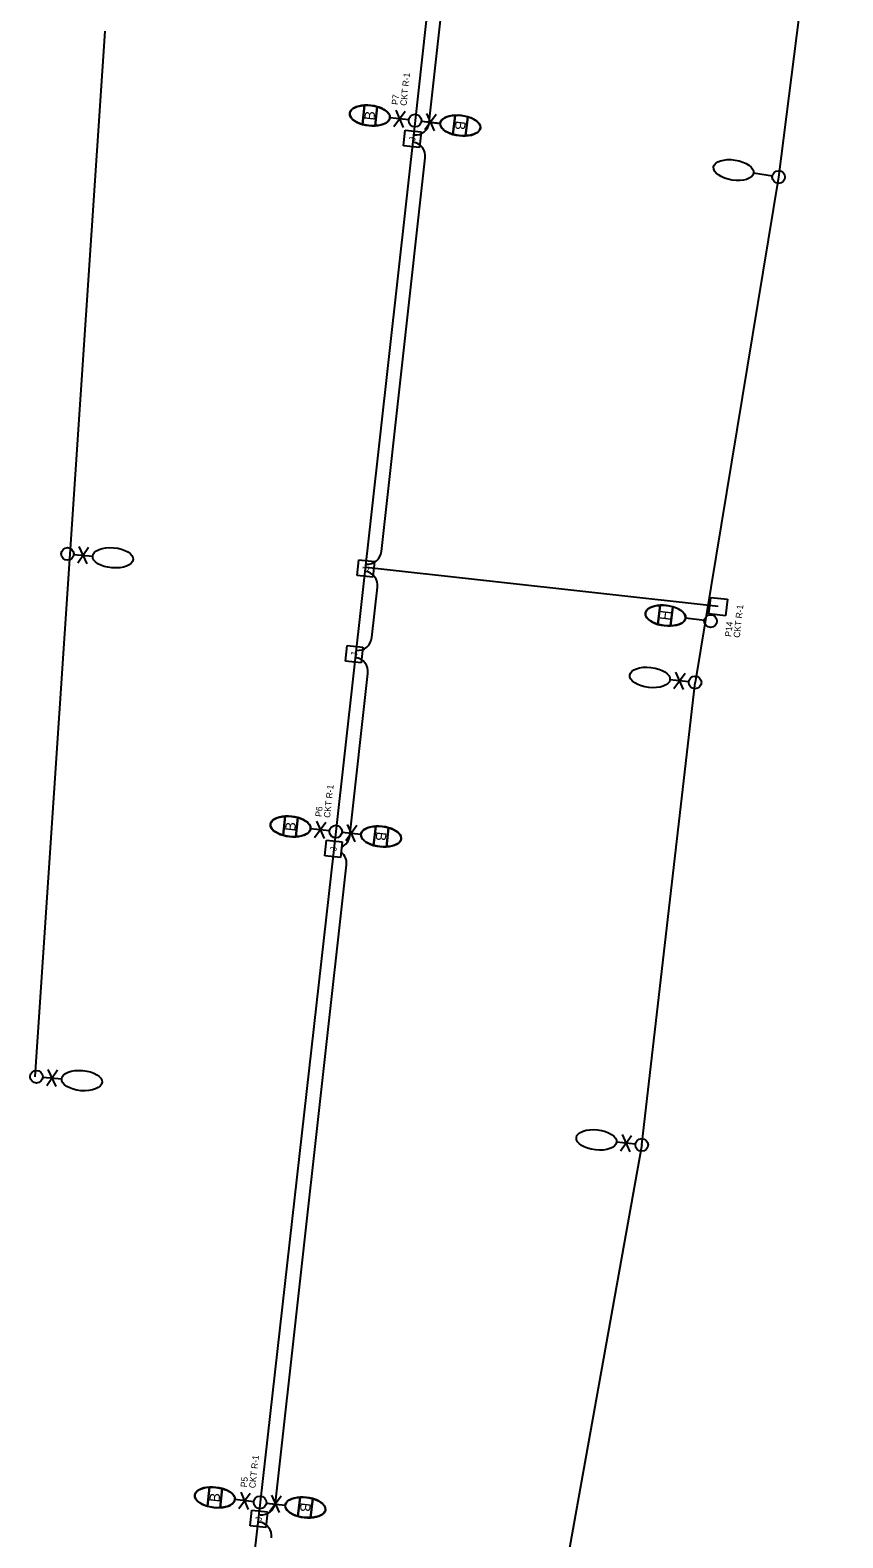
# Model space of a CAD drawing. Extents: x 925407 to 931638, y 609358 to 637063.
# Drawn here: x 930909 to 931227, y 622289 to 622880 of the extents above; entities that cross this region are included whole.
import ezdxf

# ---------------------------------------------------------------- set-up
doc = ezdxf.new("R2010")
doc.units = 0
for name, color, linetype in [('ActivePointCell_dp', 7, 'Continuous'), ('Conduit', 7, 'Continuous'), ('ConduitDB', 7, 'Continuous'), ('ConduitOT', 7, 'Continuous'), ('JunctBoxA', 7, 'Continuous'), ('LiteCond_ep', 7, 'Continuous'), ('Miscellaneous2', 7, 'Continuous'), ('PoleLight', 7, 'Continuous'), ('PoleLight_ep', 7, 'Continuous'), ('PullBox', 7, 'Continuous'), ('TextLabel', 7, 'Continuous')]:
    doc.layers.add(name, color=color, linetype=linetype)

msp = doc.modelspace()

# ---------------------------------------------------------------- linework, layer by layer
at = {"layer": 'Conduit'}
msp.add_line((931226.92, 623020.01), (931201.78, 622822.13), dxfattribs=at)
at = {"layer": 'ConduitDB'}
msp.add_line((931178.15, 622653.99), (931040.39, 622669.34), dxfattribs=at)
at = {"layer": 'ConduitOT'}
for p, q in [((931065.05, 622843.65), (931095.06, 623112.98)), ((931046.33, 622675.63), (931063.49, 622829.62)), ((931042.57, 622641.9), (931044.77, 622661.6)), ((931033.93, 622564.31), (931041.01, 622627.87)), ((931004.83, 622303.15), (931032.65, 622552.87))]:
    msp.add_line(p, q, dxfattribs=at)
for centre, start, end in [((931059.57, 622844.1), 264.8132, 355.29195), ((931058.03, 622830.35), 352.33293, 83.10011), ((931040.85, 622676.08), 264.8132, 355.29195), ((931039.31, 622662.33), 352.33293, 83.10011), ((931037.09, 622642.35), 264.8132, 355.29195), ((931035.55, 622628.6), 352.33293, 83.10011), ((931028.46, 622564.91), 295.25612, 353.6425), ((931027.19, 622553.48), 353.6425, 51.88491), ((930999.38, 622303.92), 264.8132, 351.99305), ((930997.85, 622290.17), 352.33293, 83.10011)]:
    msp.add_arc(centre, 5.5, start, end, dxfattribs=at)
at = {"layer": 'LiteCond_ep'}
for p, q in [((931090.52, 623122.74), (931059.5, 622844.27)), ((930910.79, 622469.96), (930938.27, 622879.32)), ((931059.5, 622844.27), (931028.48, 622565.95)), ((931201.78, 622822.13), (931169.11, 622624.29)), ((931148.21, 622443.26), (931169.11, 622624.29)), ((931028.48, 622565.95), (930998.82, 622303.42)), ((931148.21, 622443.26), (931092.21, 622130.66)), ((930998.82, 622303.42), (930969.37, 622039.11))]:
    msp.add_line(p, q, dxfattribs=at)
at = {"layer": 'Miscellaneous2'}
for p, q in [((931039.72, 622850.25), (931038.89, 622842.78)), ((931039.72, 622850.25), (931039.72, 622850.25)), ((931043.86, 622842.23), (931044.69, 622849.7)), ((931044.69, 622849.7), (931044.69, 622849.7)), ((931075.14, 622846.31), (931074.31, 622838.84)), ((931075.14, 622846.31), (931075.14, 622846.31)), ((931079.28, 622838.28), (931080.11, 622845.75)), ((931080.11, 622845.75), (931080.11, 622845.75)), ((931155.46, 622654.51), (931154.55, 622647.05)), ((931155.46, 622654.51), (931155.46, 622654.51)), ((931159.51, 622646.44), (931160.42, 622653.9)), ((931160.42, 622653.9), (931160.42, 622653.9)), ((931008.7, 622571.93), (931007.87, 622564.47)), ((931008.7, 622571.93), (931008.7, 622571.93)), ((931012.84, 622563.91), (931013.67, 622571.38)), ((931013.67, 622571.38), (931013.67, 622571.38)), ((931044.12, 622567.99), (931043.29, 622560.52)), ((931044.12, 622567.99), (931044.12, 622567.99)), ((931048.26, 622559.97), (931049.09, 622567.44)), ((931049.09, 622567.44), (931049.09, 622567.44)), ((930979.07, 622309.28), (930978.24, 622301.81)), ((930979.07, 622309.28), (930979.07, 622309.28)), ((930983.2, 622301.25), (930984.04, 622308.72)), ((930984.04, 622308.72), (930984.04, 622308.72)), ((931014.49, 622305.33), (931013.66, 622297.86)), ((931014.49, 622305.33), (931014.49, 622305.33)), ((931018.63, 622297.31), (931019.46, 622304.78)), ((931019.46, 622304.78), (931019.46, 622304.78))]:
    msp.add_line(p, q, dxfattribs=at)
for centre, major_axis, start_param, end_param in [((931041.79, 622846.24), (7.87, -0.88), 1.249648, 1.891946), ((931077.21, 622842.3), (7.87, -0.88), 1.249648, 1.891946), ((931041.79, 622846.24), (7.87, -0.88), 4.391241, 4.391271), ((931041.79, 622846.24), (7.87, -0.88), 4.391271, 5.033538), ((931077.21, 622842.3), (7.87, -0.88), 4.391241, 4.391271), ((931077.21, 622842.3), (7.87, -0.88), 4.391271, 5.033538), ((931157.49, 622650.47), (7.86, -0.96), 1.249648, 1.891946), ((931157.49, 622650.47), (7.86, -0.96), 4.391241, 4.391271), ((931157.49, 622650.47), (7.86, -0.96), 4.391271, 5.033538), ((931010.77, 622567.92), (7.87, -0.88), 1.249648, 1.891946), ((931046.19, 622563.98), (7.87, -0.88), 1.249648, 1.891946), ((931010.77, 622567.92), (7.87, -0.88), 4.391241, 4.391271), ((931010.77, 622567.92), (7.87, -0.88), 4.391271, 5.033538), ((931046.19, 622563.98), (7.87, -0.88), 4.391241, 4.391271), ((931046.19, 622563.98), (7.87, -0.88), 4.391271, 5.033538), ((930981.14, 622305.27), (7.87, -0.88), 1.249648, 1.891946), ((930981.14, 622305.27), (7.87, -0.88), 4.391241, 4.391271), ((930981.14, 622305.27), (7.87, -0.88), 4.391271, 5.033538), ((931016.56, 622301.32), (7.87, -0.88), 1.249648, 1.891946), ((931016.56, 622301.32), (7.87, -0.88), 4.391241, 4.391271), ((931016.56, 622301.32), (7.87, -0.88), 4.391271, 5.033538)]:
    msp.add_ellipse(centre, major_axis=major_axis, ratio=0.5, start_param=start_param, end_param=end_param, dxfattribs=at)
at = {"layer": 'PoleLight'}
for p, q in [((931038.89, 622842.78), (931039.72, 622850.25)), ((931044.69, 622849.7), (931043.86, 622842.23)), ((931057.04, 622844.54), (931049.66, 622845.36)), ((931061.96, 622843.99), (931069.34, 622843.17)), ((931074.31, 622838.84), (931075.14, 622846.31)), ((931080.11, 622845.75), (931079.28, 622838.28)), ((931154.55, 622647.05), (931155.46, 622654.51)), ((931160.42, 622653.9), (931159.51, 622646.44)), ((931172.72, 622648.6), (931165.35, 622649.51)), ((931007.87, 622564.47), (931008.7, 622571.93)), ((931013.67, 622571.38), (931012.84, 622563.91)), ((931026.02, 622566.22), (931018.64, 622567.05)), ((931043.29, 622560.52), (931044.12, 622567.99)), ((931049.09, 622567.44), (931048.26, 622559.97)), ((931030.94, 622565.68), (931038.32, 622564.86)), ((930978.24, 622301.81), (930979.07, 622309.28)), ((930984.04, 622308.72), (930983.2, 622301.25)), ((930996.39, 622303.57), (930989.01, 622304.39)), ((931001.31, 622303.02), (931008.69, 622302.2)), ((931013.66, 622297.86), (931014.49, 622305.33)), ((931019.46, 622304.78), (931018.63, 622297.31))]:
    msp.add_line(p, q, dxfattribs=at)
for centre in [(931059.5, 622844.27), (931059.5, 622844.27), (931175.17, 622648.3), (931175.17, 622648.3), (931028.48, 622565.95), (931028.48, 622565.95), (930998.85, 622303.29), (930998.85, 622303.29)]:
    msp.add_circle(centre, 2.48, dxfattribs=at)
for centre, major_axis in [((931041.79, 622846.24), (7.87, -0.88)), ((931077.21, 622842.3), (7.87, -0.88)), ((931157.49, 622650.47), (7.86, -0.96)), ((931010.77, 622567.92), (7.87, -0.88)), ((931046.19, 622563.98), (7.87, -0.88)), ((930981.14, 622305.27), (7.87, -0.88)), ((931016.56, 622301.32), (7.87, -0.88))]:
    msp.add_ellipse(centre, major_axis=major_axis, ratio=0.5, dxfattribs=at)
for centre, major_axis, start_param, end_param in [((931041.79, 622846.24), (7.87, -0.88), 1.891945, 4.391241), ((931041.79, 622846.24), (7.87, -0.88), 0.847605, 1.249648), ((931041.79, 622846.24), (7.87, -0.88), 5.033538, 6.283185), ((931041.79, 622846.24), (7.87, -0.88), 0, 0.847605), ((931077.21, 622842.3), (7.87, -0.88), 1.891945, 4.391241), ((931077.21, 622842.3), (7.87, -0.88), 0.847605, 1.249648), ((931077.21, 622842.3), (7.87, -0.88), 0, 0.847605), ((931077.21, 622842.3), (7.87, -0.88), 5.033538, 6.283185), ((931157.49, 622650.47), (7.86, -0.96), 1.891945, 4.391241), ((931157.49, 622650.47), (7.86, -0.96), 5.033538, 6.283185), ((931157.49, 622650.47), (7.86, -0.96), 0.847605, 1.249648), ((931157.49, 622650.47), (7.86, -0.96), 0, 0.847605), ((931010.77, 622567.92), (7.87, -0.88), 1.891945, 4.391241), ((931010.77, 622567.92), (7.87, -0.88), 5.033538, 6.283185), ((931010.77, 622567.92), (7.87, -0.88), 0.847605, 1.249648), ((931010.77, 622567.92), (7.87, -0.88), 0, 0.847605), ((931046.19, 622563.98), (7.87, -0.88), 1.891945, 4.391241), ((931046.19, 622563.98), (7.87, -0.88), 0.847605, 1.249648), ((931046.19, 622563.98), (7.87, -0.88), 0, 0.847605), ((931046.19, 622563.98), (7.87, -0.88), 5.033538, 6.283185), ((930981.14, 622305.27), (7.87, -0.88), 1.891945, 4.391241), ((930981.14, 622305.27), (7.87, -0.88), 0.847605, 1.249648), ((930981.14, 622305.27), (7.87, -0.88), 0, 0.847605), ((930981.14, 622305.27), (7.87, -0.88), 5.033538, 6.283185), ((931016.56, 622301.32), (7.87, -0.88), 1.891945, 4.391241), ((931016.56, 622301.32), (7.87, -0.88), 5.033538, 6.283185), ((931016.56, 622301.32), (7.87, -0.88), 0.847605, 1.249648), ((931016.56, 622301.32), (7.87, -0.88), 0, 0.847605)]:
    msp.add_ellipse(centre, major_axis=major_axis, ratio=0.5, start_param=start_param, end_param=end_param, dxfattribs=at)
at = {"layer": 'PoleLight_ep'}
for p, q in [((931057.04, 622844.54), (931049.66, 622845.34)), ((931051.22, 622841.9), (931055.61, 622847.89)), ((931051.92, 622848.29), (931054.91, 622841.49)), ((931061.96, 622844), (931069.34, 622843.19)), ((931067.77, 622846.64), (931063.38, 622840.65)), ((931067.08, 622840.25), (931064.08, 622847.04)), ((931199.33, 622822.51), (931191.99, 622823.66)), ((930925.93, 622674.41), (930933.33, 622673.78)), ((930931.75, 622677.14), (930927.51, 622671.05)), ((930931.21, 622670.73), (930928.05, 622677.46)), ((931166.65, 622624.56), (931159.27, 622625.38)), ((931160.76, 622621.98), (931165.16, 622627.96)), ((931161.47, 622628.37), (931164.45, 622621.57)), ((931026.02, 622566.2), (931018.63, 622567.01)), ((931020.2, 622563.56), (931024.59, 622569.55)), ((931020.9, 622569.95), (931023.89, 622563.16)), ((931036.75, 622568.3), (931032.36, 622562.31)), ((931036.05, 622561.91), (931033.06, 622568.71)), ((931030.94, 622565.66), (931038.32, 622564.86)), ((930919.62, 622472.47), (930915.38, 622466.38)), ((930919.08, 622466.07), (930915.92, 622472.79)), ((930913.8, 622469.74), (930921.2, 622469.11)), ((931145.75, 622443.53), (931138.37, 622444.35)), ((931139.86, 622440.95), (931144.26, 622446.93)), ((931140.57, 622447.34), (931143.55, 622440.54)), ((930990.55, 622300.95), (930994.94, 622306.94)), ((930991.25, 622307.34), (930994.24, 622300.55)), ((930996.37, 622303.59), (930988.99, 622304.4)), ((931001.29, 622303.05), (931008.67, 622302.24)), ((931007.11, 622305.69), (931002.72, 622299.7)), ((931006.41, 622299.3), (931003.42, 622306.09))]:
    msp.add_line(p, q, dxfattribs=at)
for centre, radius in [((931059.5, 622844.27), 2.48), ((931201.78, 622822.13), 2.47), ((930923.47, 622674.62), 2.47), ((931169.11, 622624.29), 2.48), ((931028.48, 622565.93), 2.48), ((930911.33, 622469.95), 2.47), ((931148.21, 622443.26), 2.48), ((930998.83, 622303.32), 2.48)]:
    msp.add_circle(centre, radius, dxfattribs=at)
for centre, major_axis in [((931041.78, 622846.21), (-7.87, 0.86)), ((931077.21, 622842.33), (7.87, -0.86)), ((931184.17, 622824.88), (-7.83, 1.22)), ((930941.22, 622673.11), (7.89, -0.67)), ((931151.4, 622626.26), (-7.87, 0.88)), ((931010.76, 622567.87), (-7.87, 0.86)), ((931046.19, 622563.99), (7.87, -0.86)), ((930929.09, 622468.44), (7.89, -0.67)), ((931130.5, 622445.23), (-7.87, 0.88)), ((930981.12, 622305.26), (-7.87, 0.86)), ((931016.54, 622301.38), (7.87, -0.86))]:
    msp.add_ellipse(centre, major_axis=major_axis, ratio=0.5, dxfattribs=at)
at = {"layer": 'PullBox'}
for p, q in [((931055.03, 622834.31), (931055.68, 622840.47)), ((931055.68, 622840.47), (931061.84, 622839.82)), ((931061.84, 622839.82), (931061.19, 622833.66)), ((931061.19, 622833.66), (931055.03, 622834.31)), ((931036.8, 622666.15), (931037.45, 622672.3)), ((931037.45, 622672.3), (931043.61, 622671.65)), ((931043.61, 622671.65), (931042.96, 622665.49)), ((931042.96, 622665.49), (931036.8, 622666.15)), ((931174.53, 622651.1), (931175.26, 622657.61)), ((931175.26, 622657.61), (931181.77, 622656.88)), ((931181.77, 622656.88), (931181.04, 622650.37)), ((931181.04, 622650.37), (931174.53, 622651.1)), ((931032.23, 622632.65), (931032.88, 622638.81)), ((931032.88, 622638.81), (931039.04, 622638.16)), ((931039.04, 622638.16), (931038.39, 622632)), ((931038.39, 622632), (931032.23, 622632.65)), ((931024.2, 622556.39), (931024.85, 622562.55)), ((931024.85, 622562.55), (931031.01, 622561.9)), ((931031.01, 622561.9), (931030.36, 622555.74)), ((931030.36, 622555.74), (931024.2, 622556.39)), ((930994.93, 622294.1), (930995.58, 622300.26)), ((930995.58, 622300.26), (931001.74, 622299.61)), ((931001.74, 622299.61), (931001.08, 622293.45)), ((931001.08, 622293.45), (930994.93, 622294.1))]:
    msp.add_line(p, q, dxfattribs=at)

# ---------------------------------------------------------------- texts
at = {"layer": 'ActivePointCell_dp'}
for s, p in [('CKT R-1', (931056.12, 622849.93)), ('P7', (931052.79, 622850.3)), ('CKT R-1', (931186.57, 622641.68)), ('P14', (931183.24, 622642.05)), ('CKT R-1', (931026.22, 622571.2)), ('P6', (931022.89, 622571.57)), ('CKT R-1', (930996.98, 622308.75)), ('P5', (930993.65, 622309.12))]:
    msp.add_text(s, height=2.5, rotation=83.6425, dxfattribs=at).set_placement(p)
at = {"layer": 'JunctBoxA'}
for p in [(931059.58, 622836.1), (931041.35, 622667.93), (931036.78, 622634.44), (931028.75, 622558.18), (930999.47, 622295.89)]:
    msp.add_text('J', height=2.48, rotation=83.95697, dxfattribs=at).set_placement(p)
at = {"layer": 'TextLabel'}
for s, rotation, p in [('B', 83.646, (931043.57, 622844.2)), ('B', 263.646, (931075.42, 622844.33)), ('H', 83.0027, (931159.25, 622648.41)), ('B', 83.646, (931012.55, 622565.89)), ('B', 263.646, (931044.4, 622566.02)), ('B', 83.646, (930982.92, 622303.23)), ('B', 263.646, (931014.77, 622303.36))]:
    msp.add_text(s, height=4, rotation=rotation, dxfattribs=at).set_placement(p)

doc.saveas('drawing.dxf')
